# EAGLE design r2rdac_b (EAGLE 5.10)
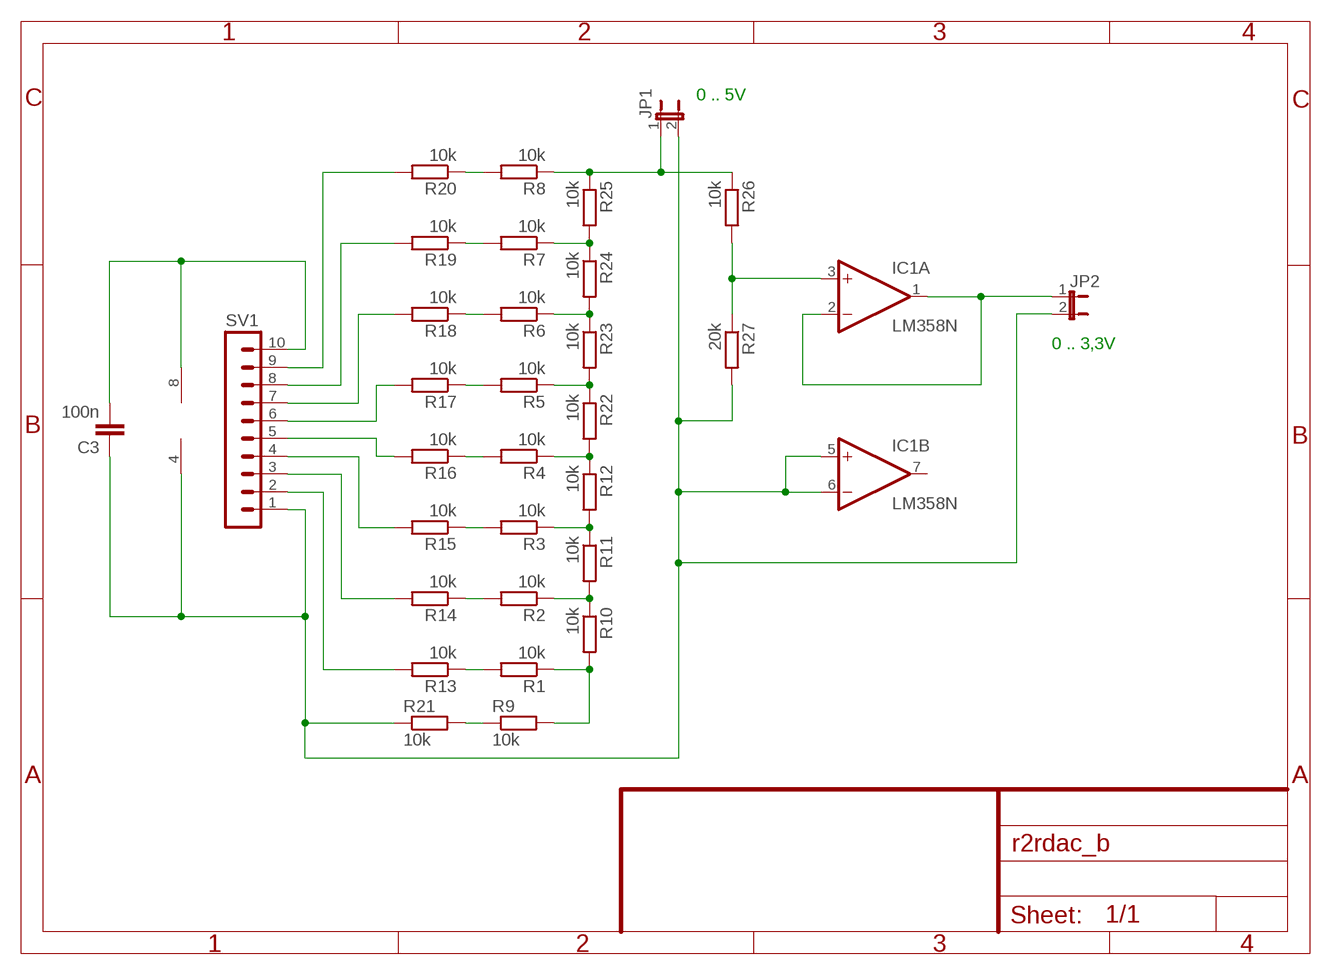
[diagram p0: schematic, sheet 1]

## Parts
C3  100n  C-EU050-025X075  [C050-025X075]
IC1  LM358N  [DIL08]
JP1  JP1E  [JP1]
JP2  JP1E  [JP1]
R1  10k  R-EU_0207/10  [0207/10]
R2  10k  R-EU_0207/10  [0207/10]
R3  10k  R-EU_0207/10  [0207/10]
R4  10k  R-EU_0207/10  [0207/10]
R5  10k  R-EU_0207/10  [0207/10]
R6  10k  R-EU_0207/10  [0207/10]
R7  10k  R-EU_0207/10  [0207/10]
R8  10k  R-EU_0207/10  [0207/10]
R9  10k  R-EU_0207/10  [0207/10]
R10  10k  R-EU_0207/10  [0207/10]
R11  10k  R-EU_0207/10  [0207/10]
R12  10k  R-EU_0207/10  [0207/10]
R13  10k  R-EU_0207/10  [0207/10]
R14  10k  R-EU_0207/10  [0207/10]
R15  10k  R-EU_0207/10  [0207/10]
R16  10k  R-EU_0207/10  [0207/10]
R17  10k  R-EU_0207/10  [0207/10]
R18  10k  R-EU_0207/10  [0207/10]
R19  10k  R-EU_0207/10  [0207/10]
R20  10k  R-EU_0207/10  [0207/10]
R21  10k  R-EU_0207/10  [0207/10]
R22  10k  R-EU_0207/10  [0207/10]
R23  10k  R-EU_0207/10  [0207/10]
R24  10k  R-EU_0207/10  [0207/10]
R25  10k  R-EU_0207/10  [0207/10]
R26  10k  R-EU_0207/10  [0207/10]
R27  20k  R-EU_0207/10  [0207/10]
SV1  MA10-1W  [MA10-1W]

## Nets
N$1: R2.1 R10.1 R11.2
N$2: R3.1 R11.1 R12.2
N$3: R4.1 R12.1 R22.2
N$4: R5.1 R22.1 R23.2
N$5: R6.1 R23.1 R24.2
N$6: R7.1 R24.1 R25.2
N$7: R8.2 R20.1
N$8: JP1.1 R8.1 R25.1 R26.1
N$9: R7.2 R19.1
N$10: R6.2 R18.1
N$11: R5.2 R17.1
N$12: R4.2 R16.1
N$13: R3.2 R15.1
N$14: R2.2 R14.1
N$15: R1.2 R13.1
N$16: R1.1 R9.2 R10.2
N$17: R9.1 R21.2
N$18: R16.2 SV1.5
N$19: R15.2 SV1.4
N$20: R14.2 SV1.3
N$21: R13.2 SV1.2
N$23: R17.2 SV1.6
N$24: R18.2 SV1.7
N$25: R19.2 SV1.8
N$26: R20.2 SV1.9
N$30: IC1.3(A:+IN) R26.2 R27.1
N$32: IC1.1(A:OUT) IC1.2(A:-IN) JP2.1
VDD: C3.2 IC1.8(P:V+) SV1.10
VSS: C3.1 IC1.4(P:V-) IC1.5(B:+IN) IC1.6(B:-IN) JP1.2 JP2.2 R21.1 R27.2 SV1.1
Unconnected: IC1.7(B:OUT)

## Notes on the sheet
- 0 .. 5V
- 0 .. 3,3V

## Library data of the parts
C3 = rcl:C-EU: CAPACITOR, European symbol
IC1 = linear:LM358: OP AMP
JP1 JP2 = jumper:JP1E: JUMPER
R1-R27 = rcl:R-EU_: RESISTOR, European symbol
SV1 = con-lstb:MA10-1W: PIN HEADER

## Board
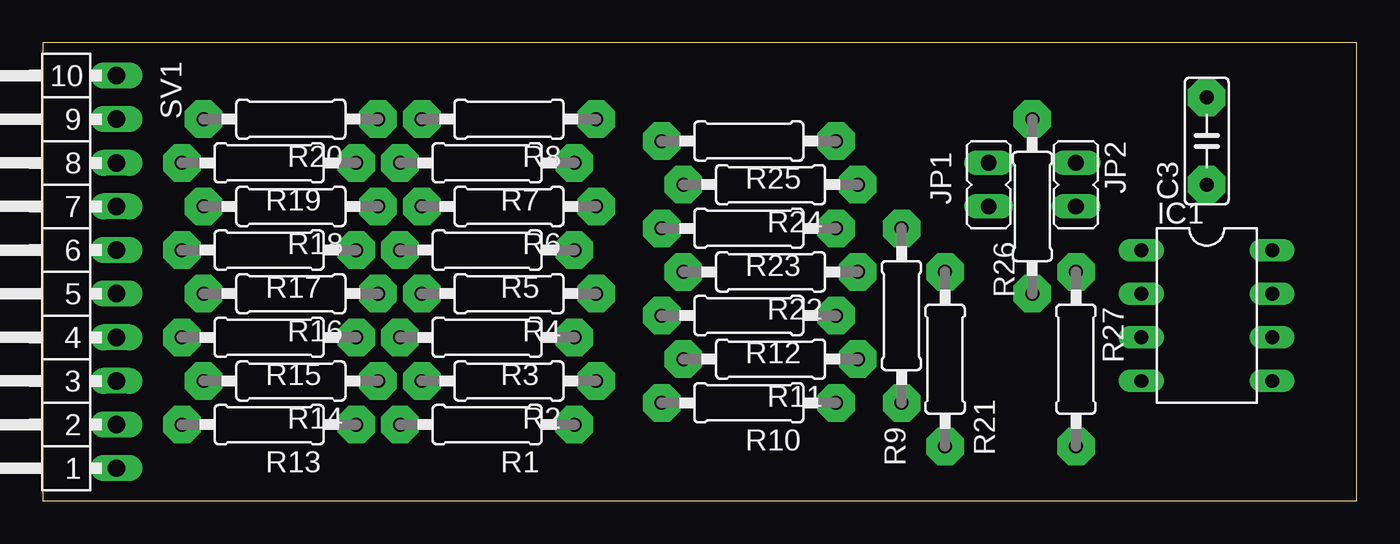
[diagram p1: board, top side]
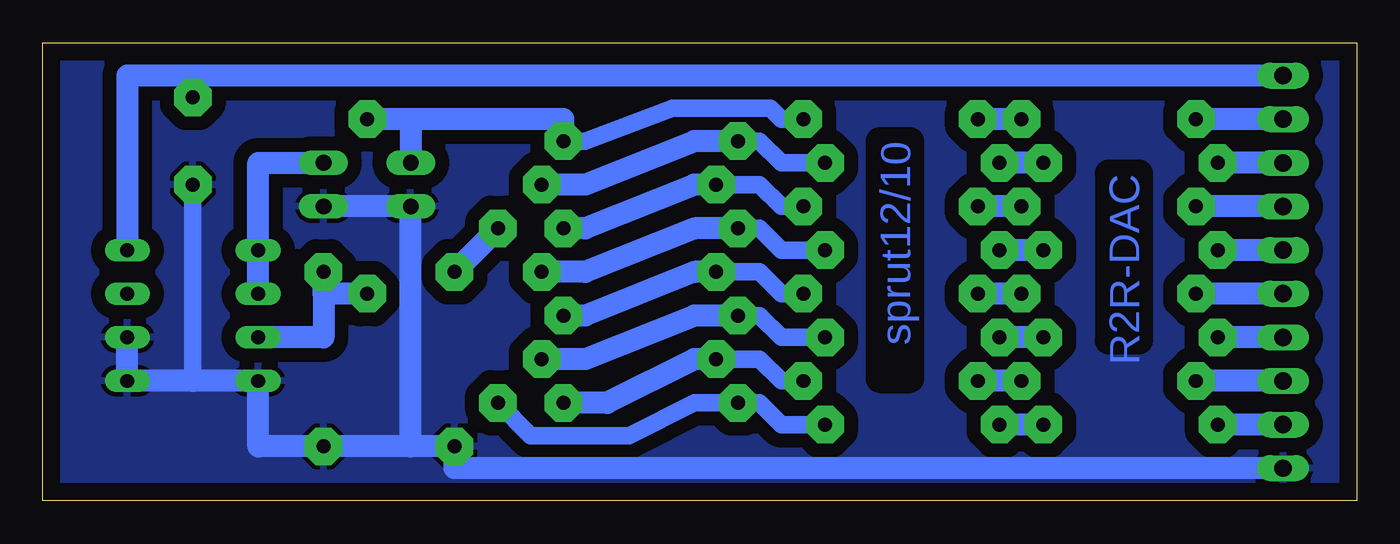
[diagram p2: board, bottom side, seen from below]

Size 76.5 x 26.66 mm. Coordinates in mm from the lower left corner, seen from the top.
Outline: 0,0 76.5,0 76.5,26.66 0,26.66 0,0
Copper layers (1*16): Top 0.035mm / dielectric 1.5mm / Bottom 0.035mm
Design rules "default": minimum track width 10mil, minimum drill 24mil, track to track 8mil, track to pad 8mil, pad to pad 8mil, via to via 8mil, smd to smd 8mil, copper to edge 40mil, drill to drill 8mil, minimum pad ring 10mil, minimum via ring 8mil, stop-mask expansion 4mil, vias tented up to drill 0mil, thermal gap 10mil

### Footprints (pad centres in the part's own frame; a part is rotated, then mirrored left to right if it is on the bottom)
C050-025X075 = drill 0.813 pad 2.184 octagon: 1 -2.54,0; 2 2.54,0
DIL08 = drill 0.813 long: 1 -3.81,-3.81; 2 -1.27,-3.81; 3 1.27,-3.81; 4 3.81,-3.81; 5 3.81,3.81; 6 1.27,3.81; 7 -1.27,3.81; 8 -3.81,3.81
JP1 = drill 0.914 long: 1 0,-1.27; 2 0,1.27
0207/10 = drill 0.813 pad 2.184 octagon: 1 -5.08,0; 2 5.08,0
MA10-1W = drill 1.016 long: 1 -11.43,0; 2 -8.89,0; 3 -6.35,0; 4 -3.81,0; 5 -1.27,0; 6 1.27,0; 7 3.81,0; 8 6.35,0; 9 8.89,0; 10 11.43,0

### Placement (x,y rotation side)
C3  67.78,20.95 90 top
IC1  67.78,10.79 270 top
JP1  55.08,18.41 180 top
JP2  60.16,18.41 180 top
R1  25.87,4.44 180 top
R2  27.14,6.98 180 top
R3  25.87,9.52 180 top
R4  27.14,12.06 180 top
R5  25.87,14.6 180 top
R6  27.14,17.14 180 top
R7  25.87,19.68 180 top
R8  27.14,22.22 180 top
R9  50,10.79 270 top
R10  41.11,5.71 180 top
R11  42.38,8.25 180 top
R12  41.11,10.79 180 top
R13  13.17,4.44 180 top
R14  14.44,6.98 180 top
R15  13.17,9.52 180 top
R16  14.44,12.06 180 top
R17  13.17,14.6 180 top
R18  14.44,17.14 180 top
R19  13.17,19.68 180 top
R20  14.44,22.22 180 top
R21  52.54,8.25 90 top
R22  42.38,13.33 180 top
R23  41.11,15.87 180 top
R24  42.38,18.41 180 top
R25  41.11,20.95 180 top
R26  57.62,17.14 270 top
R27  60.16,8.25 270 top
SV1  4.28,13.33 90 top

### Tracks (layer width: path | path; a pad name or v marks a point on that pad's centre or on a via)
N$1
  Bottom 1.016: R2.1 33.49,6.98 34.76,8.25 R11.2
  Bottom 1.27: R11.2 38.57,8.25 43.65,5.71 R10.1
N$2
  Bottom 1.016: R3.1 33.49,9.52 34.76,10.79 R12.2
  Bottom 1.27: R12.2 38.57,10.79 44.92,8.25 R11.1
N$3
  Bottom 1.016: R4.1 33.49,12.06 34.76,13.33 R22.2
  Bottom 1.27: R22.2 38.57,13.33 44.92,10.79 R12.1
N$4
  Bottom 1.016: R5.1 33.49,14.6 34.76,15.87 R23.2
  Bottom 1.27: R23.2 38.57,15.87 44.92,13.33 R22.1
N$5
  Bottom 1.016: R6.1 33.49,17.14 34.76,18.41 R24.2
  Bottom 1.27: R24.2 38.57,18.41 44.92,15.87 R23.1
N$6
  Bottom 1.016: R7.1 32.22,19.68 33.49,19.68 34.76,20.95 R25.2
  Bottom 1.27: R24.1 44.92,18.41 38.57,20.95 R25.2
N$7
  Bottom 1.27: R20.1 R8.2
N$8
  Bottom 1.016: R8.1 33.49,22.22 34.12,22.86 39.84,22.86 44.92,20.95 R25.1
  Bottom 1.27: R25.1 46.19,22.22 55.08,22.22 | 55.08,22.22 R26.1 | 55.08,22.22 JP1.1
N$9
  Bottom 1.27: R19.1 R7.2
N$10
  Bottom 1.27: R18.1 R6.2
N$11
  Bottom 1.27: R17.1 R5.2
N$12
  Bottom 1.27: R16.1 R4.2
N$13
  Bottom 1.27: R15.1 R3.2
N$14
  Bottom 1.27: R14.1 R2.2
N$15
  Bottom 1.27: R13.1 R1.2
N$16
  Bottom 1.016: R1.1 33.49,4.44 34.76,5.71 R10.2 38.57,5.71 42.38,3.8 48.09,3.8 R9.2
N$17
  Bottom 1.27: R9.1 R21.2
N$18
  Bottom 1.27: SV1.5 R16.2
N$19
  Bottom 1.27: SV1.4 R15.2
N$20
  Bottom 1.27: SV1.3 R14.2
N$21
  Bottom 1.27: SV1.2 R13.2
N$23
  Bottom 1.27: SV1.6 R17.2
N$24
  Bottom 1.27: SV1.7 R18.2
N$25
  Bottom 1.27: SV1.8 R19.2
N$26
  Bottom 1.27: SV1.9 R20.2
N$30
  Bottom 1.27: R26.2 60.16,12.06 | 60.16,12.06 60.16,9.52 IC1.3 | 60.16,12.06 R27.1
N$32
  Bottom 1.27: IC1.2 IC1.1 63.97,19.68 JP2.1
VDD
  Bottom 1.27: IC1.8 71.59,24.76 67.78,24.76 | SV1.10 67.78,24.76 | 67.78,24.76 C3.2
VSS
  Bottom 1.016: 67.78,6.98 C3.1
  Bottom 1.27: 55.08,3.17 JP1.2 JP2.2 | 55.08,3.17 R27.2 63.97,3.17 IC1.4 67.78,6.98 IC1.5 IC1.6 | SV1.1 52.54,1.9 R21.1 55.08,3.17
  pour Bottom (isolate 0.813): -0.17,27.3 77.3,27.3 77.3,-0.64 -0.17,-0.64

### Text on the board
Bottom: sprut12/10 | R2R-DAC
